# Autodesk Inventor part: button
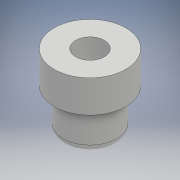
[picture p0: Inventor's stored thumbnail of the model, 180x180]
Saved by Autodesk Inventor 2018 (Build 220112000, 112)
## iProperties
Created: 2020-12
Part Number: button
Material: Genérico
Document SubType Name: Modeling
Designer: ULISES
Density: 1 g/cm^3
Appearance: Valor por defecto
Author: ULISES
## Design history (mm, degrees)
sketch "Boceto1"
  geometry: C1 r 3.75 at (0, 0); 1 further point
  constraints: 1 centre point, 1 coincident
  dimensions: "d0" = 7.5 diameter of C1
extrude "Extrusión1" new body sketch "Boceto1" distance "d1" = 7; taper "d2" = 0 deg
sketch "Boceto2"
  geometry: C1 r 3.75 at (0, 0) reference; C2 r 2 at (0, 0); C3 r 5 at (0, 0); 1 further point
  constraints: 2 centre point
  dimensions: "d3" = 4 diameter of C2; "d4" = 10 diameter of C3
extrude "Extrusión2" join sketch "Boceto2" distance "d5" = 3; taper "d6" = 0 deg
sketch "Boceto3"
  geometry: C1 r 5 at (0, 0) reference; C2 r 3.75 at (0, 0) reference; 1 further point
extrude "Extrusión3" join sketch "Boceto3" distance "d7" = 1.5; taper "d8" = 0 deg
fillet "Empalme1" dims "d9" = 1
node "Sólido1"
node "Contorno proyectado1"
